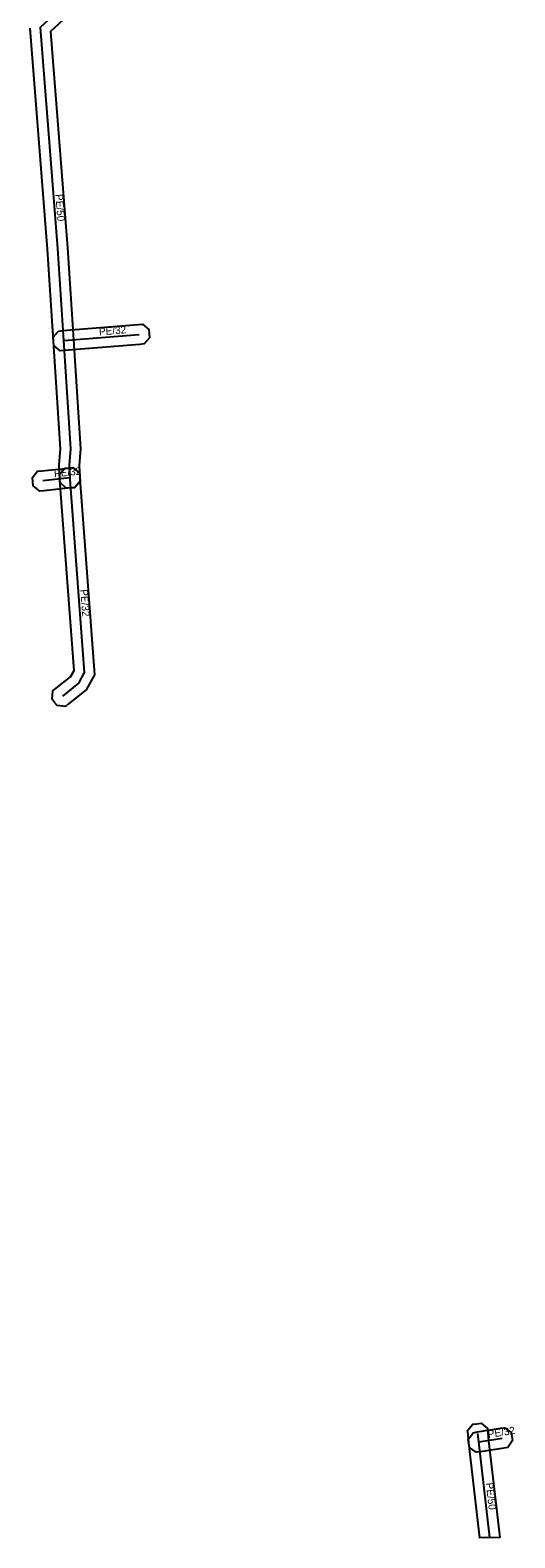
# Model space of a CAD drawing. Extents: x -682697 to -681888, y -1059966 to -1059631.
# Drawn here: x -682226.1 to -682177.6, y -1059957.4 to -1059806.3 of the extents above; entities that cross this region are included whole.
import ezdxf

# ---------------------------------------------------------------- set-up
doc = ezdxf.new("R2010")
doc.units = 0
for name, color, linetype in [('1', 7, 'Continuous'), ('24', 7, 'Continuous'), ('30', 7, 'Continuous')]:
    doc.layers.add(name, color=color, linetype=linetype)

msp = doc.modelspace()

# ---------------------------------------------------------------- linework, layer by layer
at = {"layer": '1'}
msp.add_lwpolyline([(-682222.38, -1059804.9), (-682224.09, -1059806.48), (-682222.39, -1059828.14), (-682221.79, -1059837.37), (-682221.07, -1059848.3), (-682221.22, -1059849.94), (-682221.15, -1059851.15), (-682221.13, -1059851.56), (-682221.68, -1059852.18), (-682222.09, -1059852.2), (-682222.51, -1059852.22), (-682223.13, -1059851.67), (-682223.15, -1059851.26), (-682223.22, -1059849.9), (-682223.07, -1059848.28), (-682223.79, -1059837.51), (-682224.39, -1059828.28), (-682226.13, -1059806.15)], dxfattribs=at)
for points in [[(-682223.28, -1059836.48), (-682222.87, -1059836.44), (-682215.28, -1059835.82), (-682214.87, -1059835.79), (-682214.24, -1059836.33), (-682214.2, -1059836.74), (-682214.17, -1059837.15), (-682214.71, -1059837.78), (-682215.12, -1059837.82), (-682222.71, -1059838.44), (-682223.12, -1059838.47), (-682223.75, -1059837.93), (-682223.79, -1059837.52), (-682223.82, -1059837.11)], [(-682221.64, -1059852.15), (-682222.05, -1059852.2), (-682224.76, -1059852.48), (-682225.17, -1059852.52), (-682225.81, -1059852), (-682225.85, -1059851.58), (-682225.9, -1059851.17), (-682225.38, -1059850.53), (-682224.96, -1059850.49), (-682222.25, -1059850.21), (-682221.84, -1059850.16), (-682221.2, -1059850.69), (-682221.16, -1059851.1), (-682221.11, -1059851.51)], [(-682221.18, -1059850.72), (-682221.15, -1059851.13), (-682221.14, -1059851.28), (-682219.68, -1059870.92), (-682220.51, -1059872.44), (-682222.27, -1059873.84), (-682222.59, -1059874.1), (-682223.41, -1059874.01), (-682223.67, -1059873.69), (-682223.93, -1059873.36), (-682223.84, -1059872.54), (-682223.52, -1059872.28), (-682222.07, -1059871.12), (-682221.72, -1059870.48), (-682223.14, -1059851.42), (-682223.15, -1059851.27), (-682223.18, -1059850.85), (-682222.63, -1059850.23), (-682222.22, -1059850.2), (-682221.8, -1059850.18)], [(-682180.18, -1059947.68), (-682179.06, -1059957.35), (-682181.06, -1059957.4), (-682182.16, -1059947.89), (-682182.24, -1059947.05), (-682182.29, -1059946.63), (-682181.76, -1059946), (-682181.35, -1059945.96), (-682180.93, -1059945.92), (-682180.3, -1059946.44), (-682180.26, -1059946.85)], [(-682181.73, -1059946.86), (-682181.33, -1059946.79), (-682178.99, -1059946.42), (-682178.58, -1059946.36), (-682177.91, -1059946.84), (-682177.84, -1059947.25), (-682177.78, -1059947.66), (-682178.27, -1059948.33), (-682178.67, -1059948.4), (-682181.01, -1059948.77), (-682181.42, -1059948.83), (-682182.09, -1059948.34), (-682182.16, -1059947.94), (-682182.22, -1059947.53)]]:
    msp.add_lwpolyline(points, close=True, dxfattribs=at)
at = {"layer": '24'}
for points in [[(-682223.66, -1059795.59), (-682223.63, -1059795.82), (-682223.06, -1059804.16), (-682225.13, -1059806.07), (-682223.39, -1059828.21), (-682222.79, -1059837.44), (-682222.07, -1059848.29), (-682222.22, -1059849.92), (-682222.15, -1059851.2)], [(-682222.79, -1059837.44), (-682215.2, -1059836.82)], [(-682222.15, -1059851.2), (-682224.86, -1059851.48)], [(-682222.15, -1059851.2), (-682222.14, -1059851.35), (-682220.7, -1059870.7), (-682221.29, -1059871.78), (-682222.89, -1059873.06)], [(-682180.06, -1059957.37), (-682181.17, -1059947.78), (-682181.25, -1059946.95)], [(-682181.17, -1059947.78), (-682178.83, -1059947.41)]]:
    msp.add_lwpolyline(points, dxfattribs=at)

# ---------------------------------------------------------------- texts
at = {"layer": '30'}
for s, rotation, p in [('PE/50', 274.4937, (-682223.6, -1059822.79)), ('PE/32', 4.6699, (-682219.2, -1059836.93)), ('PE/32', 5.8989, (-682223.7, -1059851.14)), ('PE/32', 274.256, (-682221.1, -1059862.39)), ('PE/32', 8.9852, (-682180.2, -1059947.4)), ('PE/50', 276.6001, (-682180.47, -1059951.91))]:
    msp.add_text(s, height=0.75, rotation=rotation, dxfattribs=at).set_placement(p)

doc.saveas('drawing.dxf')
